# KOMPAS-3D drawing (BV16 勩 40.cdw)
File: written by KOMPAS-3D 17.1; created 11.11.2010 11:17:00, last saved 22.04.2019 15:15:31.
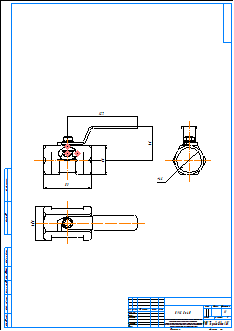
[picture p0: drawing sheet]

Sheet 1: A2, portrait

Title block, sheet 1: name: BV16 Ду 40; material: Внимание! Данный продукт является объектом авторского права ООО «Торговый Дом АДЛ». / Запрещается изменение, копирование, распространение / (в том числе путем копирования на другие сайты и ресурсы в Интернете) / или любое иное использование информации и объектов без предварительного / согласия правообладателя (ООО «Торговый Дом АДЛ»).; scale: 1:1; sheets: 1; organisation: ООО "Торговый дом АДЛ"; sheet format: A2; stored path: \\adlc.lan\data\АДЛ_ПКД\3D-модели\ADL production\Краны шаровые серии BV\BV16\KOMPAS 2D\BV16 Ду 40.cdw

Views: Спереди 1, Проекционный вид 2, Проекционный вид 3
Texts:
  user
  adl
Dimensions and other numbers on the sheet: 83; 53; 69; 127; 46; 61,2; 1:1; 1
